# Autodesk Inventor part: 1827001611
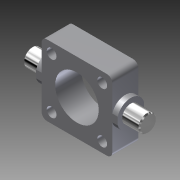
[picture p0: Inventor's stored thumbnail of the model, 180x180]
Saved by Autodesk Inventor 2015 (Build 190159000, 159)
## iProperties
Created: 2012-12
Part Number: 1827001611
Material: Generic
Document SubType Name: Modeling
Designer: Marci
Density: 1 g/cm^3
Appearance: Default
Translation Standard: STEP AP214IS
FileName: 1827001611
PreProcessor: PRO/ENGINEER BY PARAMETRIC TECHNOLOGY CORPORATION, 2006020
PostProcessor: Build: 160, Release: 2012 RTM - Date: Tue 03/01/2011
Sent Units: millimeter
Uncertainty: 0.01276685252536
Author: Marci
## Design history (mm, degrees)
node "18270016111"
node "1827001611"
node "Base1"
